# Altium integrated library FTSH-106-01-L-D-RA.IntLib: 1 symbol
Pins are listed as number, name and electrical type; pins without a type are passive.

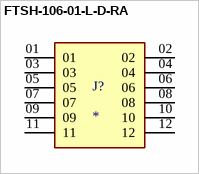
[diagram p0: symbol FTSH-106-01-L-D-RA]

## FTSH-106-01-L-D-RA
designator J?
MF: Samtec; MP: FTSH-106-01-L-D-RA
footprint SAMTEC_FTSH-106-01-L-D-RA
pins: 01, 02, 03, 04, 05, 06, 07, 08, 09, 10, 11, 12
